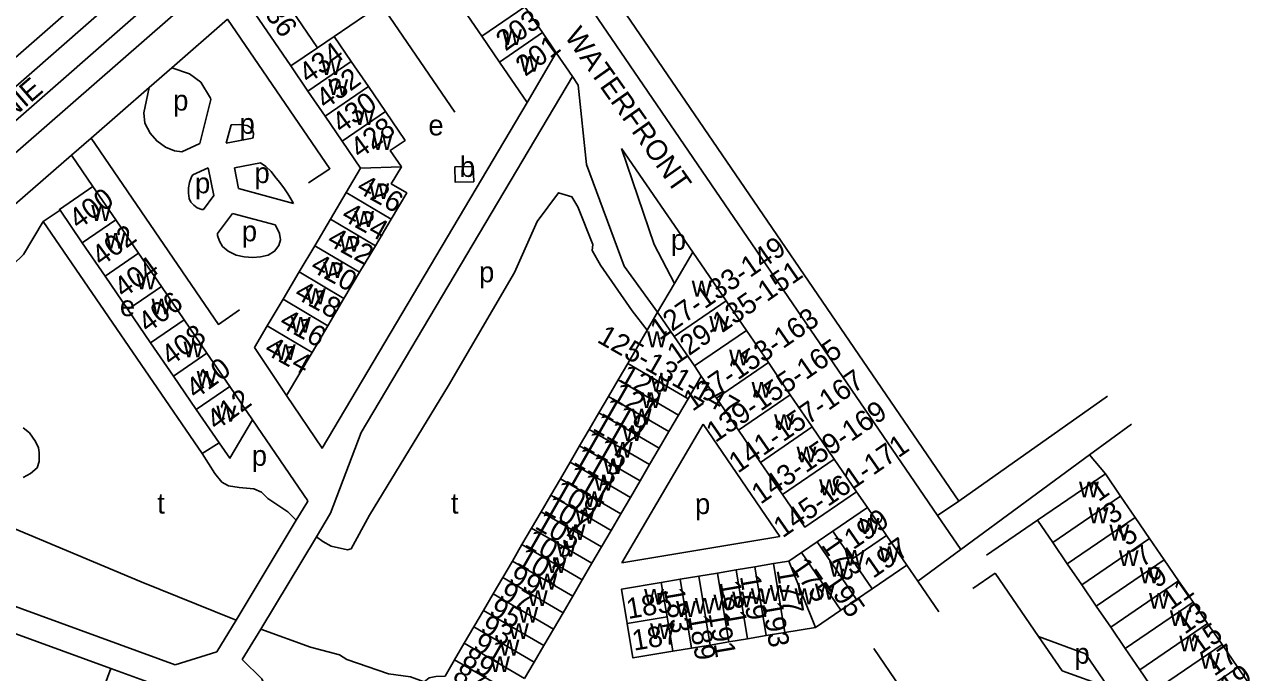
# Model space of a CAD drawing. Extents: x 154320 to 156262, y 382651 to 384180.
# Drawn here: x 156007.7 to 156246.7, y 383180.7 to 383306.8 of the extents above; entities that cross this region are included whole.
import ezdxf

# ---------------------------------------------------------------- set-up
doc = ezdxf.new("R2010")
doc.units = 0
for name, color, linetype in [('BLT_Basislijn', 7, 'Continuous'), ('BLT_Bebouwing', 7, 'Continuous'), ('BLT_Centroide', 7, 'Continuous'), ('BLT_Huisnummer', 7, 'Continuous'), ('BLT_Huisnummer_ tussenligend', 7, 'Continuous'), ('BLT_Huisnummer_reeks', 7, 'Continuous'), ('BLT_Onderverdeling_panden', 7, 'Continuous'), ('BLT_Straatnaam', 7, 'Continuous')]:
    doc.layers.add(name, color=color, linetype=linetype)

msp = doc.modelspace()

# ---------------------------------------------------------------- linework, layer by layer
at = {"layer": 'BLT_Basislijn'}
for p, q in [((156057.41, 383339.79), (155935.41, 383232.93)), ((155937.39, 383240.46), (156050.24, 383339.15)), ((156060.26, 383335.64), (155938.63, 383229.11)), ((155946.6, 383229.91), (156059.86, 383328.96)), ((156036.31, 383298.35), (156047.19, 383307.85)), ((156111.11, 383301.29), (156114.23, 383296.66)), ((156031.9, 383294.51), (156036.31, 383298.35)), ((156073.18, 383227.36), (156114.23, 383296.66)), ((156114.23, 383296.66), (156115.37, 383294.97)), ((156020.62, 383284.67), (156031.9, 383294.51)), ((156016.82, 383281.36), (156020.62, 383284.67)), ((156123.8, 383282.68), (156137.65, 383262.47)), ((155942.48, 383216.52), (156016.82, 383281.36)), ((156021, 383275.24), (156016.82, 383281.36)), ((156049.33, 383274.89), (156060.01, 383271.96)), ((156011.34, 383268.41), (156014.6, 383270.63)), ((156042.22, 383223.28), (156011.34, 383268.41)), ((156048.17, 383270.02), (156056.42, 383267.76)), ((156218.33, 383234.45), (156189.4, 383214.02)), ((156052.03, 383229.82), (156062.77, 383214.03)), ((156222.99, 383228.97), (156214.82, 383223.01)), ((156045.52, 383225.37), (156042.22, 383223.28)), ((156217.89, 383219.31), (156214.82, 383223.01)), ((156171.6, 383212.78), (156169.51, 383215.84)), ((156185.27, 383211.2), (156189.78, 383204.59)), ((156060.54, 383210.27), (156048.84, 383190.84)), ((156204.7, 383210.29), (156194.79, 383203.51)), ((156064.46, 383207.08), (156053.63, 383189.1)), ((156181.42, 383198.44), (156179.28, 383201.56)), ((156181.42, 383198.44), (156185.5, 383192.48)), ((156048.84, 383190.84), (156045.11, 383184.66)), ((156053.63, 383189.1), (156050.04, 383183.15)), ((156045.11, 383184.66), (156037.02, 383182.14)), ((156177.97, 383177.79), (156172.89, 383185.3)), ((156022.72, 383176.68), (156024.45, 383181.39)), ((156036.57, 383176.99), (156024.45, 383181.39))]:
    msp.add_line(p, q, dxfattribs=at)
for points in [[(156189.4, 383214.02), (156098.19, 383347.67)], [(156185.27, 383211.2), (156093.74, 383345.32)], [(156067.93, 383304.46), (156077.07, 383310.67), (156091.4, 383289.75)], [(156062.9, 383275.95), (156067.08, 383278.7), (156047.19, 383307.85)], [(156036.31, 383298.35), (156039.76, 383297.21), (156041.95, 383295.54), (156043.89, 383292.43), (156043.95, 383292.17)], [(156038.3, 383282.02), (156036.87, 383282.21), (156035.08, 383282.94), (156033.42, 383284.13), (156032.12, 383285.62), (156031.12, 383287.55), (156030.89, 383289.59), (156031.9, 383294.51)], [(156130.82, 383250.76), (156124.28, 383259.77), (156117, 383279.53), (156115.37, 383294.97)], [(156043.95, 383292.17), (156041.76, 383283.65), (156038.3, 383282.02)], [(156058.63, 383234.59), (156065.55, 383224.29), (156105.42, 383291.59)], [(156047.85, 383287.25), (156046.93, 383283.68)], [(156047.85, 383287.25), (156049.42, 383287.29), (156050.97, 383287.14), (156051.58, 383286.77), (156051.95, 383286.32), (156052.2, 383285.59), (156052.15, 383284.88), (156052.05, 383284.66)], [(156049.52, 383251.22), (156045.4, 383248.4), (156020.62, 383284.67)], [(156046.93, 383283.68), (156052.05, 383284.66)], [(156123.8, 383282.68), (156130.16, 383263.99), (156134.1, 383256.39)], [(156048.51, 383278.89), (156053.59, 383279.87)], [(156053.59, 383279.87), (156054.59, 383279.12), (156055.63, 383278.18), (156056.38, 383277.23), (156057.27, 383276.1), (156058.11, 383275), (156058.89, 383273.8), (156059.49, 383272.83), (156060.01, 383271.96)], [(156042.47, 383270.76), (156042.18, 383270.79), (156041.29, 383271.13), (156040.63, 383271.59), (156040.06, 383272.23), (156039.74, 383272.9), (156039.59, 383273.96), (156039.61, 383275.02), (156039.78, 383276.05), (156040.18, 383277.14), (156040.43, 383277.49)], [(156043.4, 383278.89), (156040.43, 383277.49)], [(156043.4, 383278.89), (156044.52, 383273.48), (156042.47, 383270.76)], [(156048.51, 383278.89), (156049.33, 383274.89)], [(156128.8, 383247.3), (156125.88, 383251.06), (156119.69, 383259.91), (156118.07, 383262.77), (156118.2, 383263.93), (156115.32, 383271.29), (156114.16, 383273.25), (156111.53, 383274.02), (156107.4, 383268.42), (156102.97, 383258.52), (156090.17, 383236.5), (156074.81, 383211.3), (156071.19, 383204.72), (156070.5, 383204.54), (156067.32, 383205.25), (156065.68, 383206.13), (156064.46, 383207.08)], [(156011.34, 383268.41), (156007.52, 383261.99), (155996.87, 383251.78), (155973.79, 383231.77), (155972.23, 383231.52), (155970.88, 383231.79), (155962.55, 383224.45), (155964.02, 383223.22), (155980.92, 383216.77), (155985.15, 383215.38), (155987.15, 383215.65), (156001.25, 383210.49), (156030.38, 383198.26), (156048.23, 383191.07), (156048.84, 383190.84)], [(156048.17, 383270.02), (156045.21, 383266.1)], [(156056.42, 383267.76), (156056.77, 383267.21), (156057.27, 383266.08), (156057.48, 383264.85), (156057.14, 383263.74), (156056.31, 383262.65), (156055.09, 383261.91), (156053.57, 383261.59), (156052.06, 383261.43), (156050.41, 383261.57), (156048.87, 383261.87), (156047.3, 383262.64), (156046.21, 383263.59), (156045.58, 383264.61), (156045.25, 383265.69), (156045.21, 383266.1)], [(156007.4, 383228.29), (156008.63, 383227.29), (156009.83, 383225.59), (156010.41, 383224.37), (156010.54, 383223.49), (156010.56, 383221.73), (156010.14, 383220.49), (156008.87, 383219.39), (156007.44, 383218.57)], [(156073.18, 383227.36), (156067.21, 383211.65), (156064.46, 383207.08)], [(156123.87, 383201.97), (156139.64, 383229)], [(156139.64, 383229), (156154.61, 383207.11)], [(156060.54, 383210.27), (156058.91, 383211.92), (156054.99, 383214.52), (156053.8, 383215.75), (156052.26, 383216.37), (156049.41, 383216.67), (156047.33, 383216.97), (156046.08, 383217.7), (156044.71, 383219.36), (156042.22, 383223.28)], [(156214.82, 383223.01), (156189.78, 383204.59)], [(156062.77, 383214.03), (156062.7, 383213.85), (156060.54, 383210.27)], [(156189.4, 383214.02), (156185.27, 383211.2)], [(155960.94, 383209.9), (156026.16, 383186.09), (156037.02, 383182.14)], [(156154.61, 383207.11), (156123.87, 383201.97)], [(156024.45, 383181.39), (155960.61, 383204.7), (155940.61, 383200.09)], [(156189.78, 383204.59), (156181.42, 383198.44)], [(156196.45, 383200.01), (156192.09, 383197.02)], [(156204.88, 383187.64), (156196.45, 383200.01)], [(156053.63, 383189.1), (156063.31, 383185.56), (156068.94, 383184.05), (156070.37, 383183.18), (156078.47, 383180.38), (156082.76, 383179.81), (156085.39, 383178.84), (156086.36, 383179.59), (156087.7, 383179.88), (156089.47, 383179.91)], [(156204.88, 383187.64), (156214.01, 383184.3), (156218.52, 383177.7)], [(156218.52, 383177.7), (156209.49, 383180.97), (156204.88, 383187.64)], [(156055.87, 383175.29), (156053.84, 383179.39), (156050.04, 383183.15)]]:
    msp.add_lwpolyline(points, dxfattribs=at)
at = {"layer": 'BLT_Bebouwing'}
for p, q in [((156064.64, 383302.23), (156059.65, 383309.57)), ((156093.18, 383309.52), (156096.61, 383304.5)), ((156108.44, 383305.2), (156105.01, 383310.22)), ((156067.93, 383304.46), (156064.64, 383302.23)), ((156071.24, 383299.59), (156067.93, 383304.46)), ((156096.61, 383304.5), (156100.04, 383299.47)), ((156111.11, 383301.29), (156108.44, 383305.2)), ((156074.56, 383294.71), (156071.24, 383299.59)), ((156059.47, 383298.72), (156062.8, 383293.84)), ((156077.89, 383289.82), (156074.56, 383294.71)), ((156062.8, 383293.84), (156066.14, 383288.96)), ((156066.14, 383288.96), (156069.47, 383284.07)), ((156069.47, 383284.07), (156073.06, 383278.81)), ((156073.06, 383278.81), (156070.26, 383274.07)), ((156070.26, 383274.07), (156067.19, 383268.89)), ((156014.6, 383270.63), (156018.92, 383264.3)), ((156029.87, 383262.26), (156025.44, 383268.75)), ((156067.19, 383268.89), (156064.13, 383263.73)), ((156075.92, 383263.71), (156078.99, 383268.89)), ((156018.92, 383264.3), (156023.36, 383257.81)), ((156064.13, 383263.73), (156061.09, 383258.61)), ((156072.86, 383258.55), (156075.92, 383263.71)), ((156034.3, 383255.77), (156029.87, 383262.26)), ((156061.09, 383258.61), (156057.96, 383253.32)), ((156069.82, 383253.43), (156072.86, 383258.55)), ((156023.36, 383257.81), (156027.79, 383251.32)), ((156134.1, 383256.39), (156130.82, 383250.76)), ((156038.73, 383249.29), (156034.3, 383255.77)), ((156027.79, 383251.32), (156032.22, 383244.83)), ((156057.96, 383253.32), (156054.89, 383248.14)), ((156066.68, 383248.15), (156069.82, 383253.43)), ((156043.17, 383242.8), (156038.73, 383249.29)), ((156130.82, 383250.76), (156128.8, 383247.3)), ((156063.6, 383242.96), (156066.68, 383248.15)), ((156128.8, 383247.3), (156125, 383240.79)), ((156032.22, 383244.83), (156036.65, 383238.35)), ((156047.6, 383236.31), (156043.17, 383242.8)), ((156036.65, 383238.35), (156041.08, 383231.86)), ((156207.66, 383205.95), (156204.7, 383210.29)), ((156210.48, 383201.82), (156207.66, 383205.95)), ((156213.29, 383197.7), (156210.48, 383201.82)), ((156216.11, 383193.57), (156213.29, 383197.7)), ((156218.93, 383189.44), (156216.11, 383193.57)), ((156221.76, 383185.31), (156218.93, 383189.44)), ((156224.57, 383181.19), (156221.76, 383185.31)), ((156227.39, 383177.05), (156224.57, 383181.19))]:
    msp.add_line(p, q, dxfattribs=at)
for points in [[(156059.47, 383298.72), (156050.98, 383311.16)], [(156105.42, 383291.59), (156111.11, 383301.29)], [(156100.04, 383299.47), (156105.42, 383291.59)], [(156080.98, 383279.09), (156078.81, 383282.25), (156081.7, 383284.23), (156077.89, 383289.82)], [(156078.99, 383268.89), (156082.02, 383273.99), (156079.01, 383275.78), (156080.98, 383279.09)], [(156021, 383275.24), (156014.49, 383270.79), (156014.6, 383270.63)], [(156025.44, 383268.75), (156021, 383275.24)], [(156137.65, 383262.47), (156134.1, 383256.39)], [(156144.14, 383252.97), (156137.65, 383262.47)], [(156148.07, 383247.21), (156144.14, 383252.97)], [(156054.89, 383248.14), (156052.39, 383243.93)], [(156152.35, 383240.96), (156148.07, 383247.21)], [(156052.39, 383243.93), (156058.63, 383234.59)], [(156058.63, 383234.59), (156063.6, 383242.96)], [(156125, 383240.79), (156123.13, 383237.59)], [(156156.62, 383234.71), (156152.35, 383240.96)], [(156123.13, 383237.59), (156121.26, 383234.38)], [(156136.74, 383233.94), (156139.31, 383238.34)], [(156139.31, 383238.34), (156142.24, 383234.06)], [(156052.03, 383229.82), (156047.6, 383236.31)], [(156121.26, 383234.38), (156119.39, 383231.18)], [(156160.89, 383228.45), (156156.62, 383234.71)], [(156134.87, 383230.73), (156136.74, 383233.94)], [(156142.24, 383234.06), (156146.52, 383227.8)], [(156041.08, 383231.86), (156045.52, 383225.37)], [(156045.52, 383225.37), (156047.62, 383222.34), (156052.03, 383229.82)], [(156119.39, 383231.18), (156117.52, 383227.97)], [(156133, 383227.53), (156134.87, 383230.73)], [(156117.52, 383227.97), (156115.65, 383224.77)], [(156131.13, 383224.33), (156133, 383227.53)], [(156146.52, 383227.8), (156150.79, 383221.55)], [(156165.17, 383222.2), (156160.89, 383228.45)], [(156115.65, 383224.77), (156113.78, 383221.56)], [(156129.26, 383221.12), (156131.13, 383224.33)], [(156113.78, 383221.56), (156111.91, 383218.36)], [(156127.39, 383217.92), (156129.26, 383221.12)], [(156150.79, 383221.55), (156155.07, 383215.3)], [(156169.51, 383215.84), (156165.17, 383222.2)], [(156111.91, 383218.36), (156110.04, 383215.16)], [(156125.52, 383214.71), (156127.39, 383217.92)], [(156204.7, 383210.29), (156217.89, 383219.31)], [(156217.89, 383219.31), (156220.86, 383214.97)], [(156155.07, 383215.3), (156159.41, 383208.95), (156169.51, 383215.84)], [(156110.04, 383215.16), (156108.17, 383211.95)], [(156123.65, 383211.51), (156125.52, 383214.71)], [(156220.86, 383214.97), (156223.68, 383210.84)], [(156108.17, 383211.95), (156106.3, 383208.75)], [(156121.78, 383208.31), (156123.65, 383211.51)], [(156171.6, 383212.78), (156164.87, 383208.18)], [(156175.33, 383207.34), (156171.6, 383212.78)], [(156223.68, 383210.84), (156226.5, 383206.71)], [(156106.3, 383208.75), (156104.43, 383205.54)], [(156119.91, 383205.1), (156121.78, 383208.31)], [(156164.87, 383208.18), (156161.82, 383206.1)], [(156161.82, 383206.1), (156158.78, 383204.02)], [(156179.28, 383201.56), (156175.33, 383207.34)], [(156226.5, 383206.71), (156229.32, 383202.59)], [(156104.43, 383205.54), (156102.56, 383202.34)], [(156118.04, 383201.9), (156119.91, 383205.1)], [(156158.78, 383204.02), (156156.3, 383202.32)], [(156102.56, 383202.34), (156100.69, 383199.13)], [(156116.17, 383198.69), (156118.04, 383201.9)], [(156149.71, 383201.22), (156146.07, 383200.61)], [(156153.34, 383201.83), (156149.71, 383201.22)], [(156156.3, 383202.32), (156153.34, 383201.83)], [(156172.54, 383196.96), (156179.28, 383201.56)], [(156229.32, 383202.59), (156232.14, 383198.46)], [(156100.69, 383199.13), (156098.82, 383195.93)], [(156114.3, 383195.49), (156116.17, 383198.69)], [(156135.17, 383198.79), (156131.53, 383198.18)], [(156138.8, 383199.4), (156135.17, 383198.79)], [(156142.44, 383200.01), (156138.8, 383199.4)], [(156146.07, 383200.61), (156142.44, 383200.01)], [(156131.53, 383198.18), (156123.79, 383196.89), (156124.91, 383190.19)], [(156169.49, 383194.88), (156172.54, 383196.96)], [(156232.14, 383198.46), (156234.96, 383194.33)], [(156098.82, 383195.93), (156096.95, 383192.73)], [(156112.43, 383192.28), (156114.3, 383195.49)], [(156166.44, 383192.8), (156169.49, 383194.88)], [(156234.96, 383194.33), (156237.78, 383190.21)], [(156096.95, 383192.73), (156095.08, 383189.52)], [(156110.56, 383189.08), (156112.43, 383192.28)], [(156161.49, 383189.41), (156166.44, 383192.8)], [(156095.08, 383189.52), (156093.21, 383186.32)], [(156108.69, 383185.88), (156110.56, 383189.08)], [(156124.91, 383190.19), (156126.02, 383183.48), (156133.77, 383184.78)], [(156155.58, 383188.43), (156161.49, 383189.41)], [(156237.78, 383190.21), (156240.6, 383186.08)], [(156141.04, 383185.99), (156144.68, 383186.6)], [(156144.68, 383186.6), (156148.31, 383187.21)], [(156148.31, 383187.21), (156151.95, 383187.82)], [(156151.95, 383187.82), (156155.58, 383188.43)], [(156093.21, 383186.32), (156091.34, 383183.11)], [(156106.82, 383182.67), (156108.69, 383185.88)], [(156133.77, 383184.78), (156137.41, 383185.39)], [(156137.41, 383185.39), (156141.04, 383185.99)], [(156240.6, 383186.08), (156243.64, 383181.62)], [(156091.34, 383183.11), (156089.47, 383179.91)], [(156104.95, 383179.47), (156106.82, 383182.67)], [(156243.64, 383181.62), (156246.68, 383177.17)]]:
    msp.add_lwpolyline(points, dxfattribs=at)
msp.add_lwpolyline([(156091.37, 383279.06), (156091.45, 383276.08), (156095.04, 383276.18), (156094.95, 383279.15)], close=True, dxfattribs=at)
at = {"layer": 'BLT_Onderverdeling_panden'}
for p, q in [((156096.61, 383304.5), (156105.01, 383310.22)), ((156108.44, 383305.2), (156100.04, 383299.47)), ((156059.47, 383298.72), (156064.64, 383302.23)), ((156071.24, 383299.59), (156062.8, 383293.84)), ((156066.14, 383288.96), (156074.56, 383294.71)), ((156077.89, 383289.82), (156069.47, 383284.07)), ((156073.06, 383278.81), (156080.98, 383279.09)), ((156078.99, 383268.89), (156070.26, 383274.07)), ((156018.92, 383264.3), (156025.44, 383268.75)), ((156067.19, 383268.89), (156075.92, 383263.71)), ((156072.86, 383258.55), (156064.13, 383263.73)), ((156023.36, 383257.81), (156029.87, 383262.26)), ((156061.09, 383258.61), (156069.82, 383253.43)), ((156034.3, 383255.77), (156027.79, 383251.32)), ((156066.68, 383248.15), (156057.96, 383253.32)), ((156032.22, 383244.83), (156038.73, 383249.29)), ((156054.89, 383248.14), (156063.6, 383242.96)), ((156043.17, 383242.8), (156036.65, 383238.35)), ((156041.08, 383231.86), (156047.6, 383236.31))]:
    msp.add_line(p, q, dxfattribs=at)
for points in [[(156144.14, 383252.97), (156134.03, 383246.06)], [(156130.82, 383250.76), (156134.03, 383246.06)], [(156148.07, 383247.21), (156137.97, 383240.31)], [(156134.03, 383246.06), (156137.97, 383240.31)], [(156125, 383240.79), (156136.74, 383233.94)], [(156137.97, 383240.31), (156139.31, 383238.34)], [(156152.35, 383240.96), (156142.24, 383234.06)], [(156123.13, 383237.59), (156134.87, 383230.73)], [(156121.26, 383234.38), (156133, 383227.53)], [(156156.62, 383234.71), (156146.52, 383227.8)], [(156119.39, 383231.18), (156131.13, 383224.33)], [(156117.52, 383227.97), (156129.26, 383221.12)], [(156160.89, 383228.45), (156150.79, 383221.55)], [(156115.65, 383224.77), (156127.39, 383217.92)], [(156113.78, 383221.56), (156125.52, 383214.71)], [(156165.17, 383222.2), (156155.07, 383215.3)], [(156111.91, 383218.36), (156123.65, 383211.51)], [(156110.04, 383215.16), (156121.78, 383208.31)], [(156220.86, 383214.97), (156207.66, 383205.95)], [(156108.17, 383211.95), (156119.91, 383205.1)], [(156223.68, 383210.84), (156210.48, 383201.82)], [(156106.3, 383208.75), (156118.04, 383201.9)], [(156168.59, 383202.73), (156164.87, 383208.18)], [(156169.49, 383194.88), (156161.82, 383206.1)], [(156175.33, 383207.34), (156168.59, 383202.73)], [(156226.5, 383206.71), (156213.29, 383197.7)], [(156104.43, 383205.54), (156116.17, 383198.69)], [(156166.44, 383192.8), (156158.78, 383204.02)], [(156102.56, 383202.34), (156114.3, 383195.49)], [(156151.95, 383187.82), (156149.71, 383201.22)], [(156155.58, 383188.43), (156153.34, 383201.83)], [(156156.3, 383202.32), (156161.49, 383189.41)], [(156172.54, 383196.96), (156168.59, 383202.73)], [(156229.32, 383202.59), (156216.11, 383193.57)], [(156100.69, 383199.13), (156112.43, 383192.28)], [(156137.41, 383185.39), (156135.17, 383198.79)], [(156141.04, 383185.99), (156138.8, 383199.4)], [(156144.68, 383186.6), (156142.44, 383200.01)], [(156148.31, 383187.21), (156146.07, 383200.61)], [(156132.65, 383191.48), (156131.53, 383198.18)], [(156232.14, 383198.46), (156218.93, 383189.44)], [(156098.82, 383195.93), (156110.56, 383189.08)], [(156234.96, 383194.33), (156221.76, 383185.31)], [(156096.95, 383192.73), (156108.69, 383185.88)], [(156124.91, 383190.19), (156132.65, 383191.48)], [(156133.77, 383184.78), (156132.65, 383191.48)], [(156095.08, 383189.52), (156106.82, 383182.67)], [(156237.78, 383190.21), (156224.57, 383181.19)], [(156093.21, 383186.32), (156104.95, 383179.47)], [(156240.6, 383186.08), (156227.39, 383177.05)], [(156091.34, 383183.11), (156103.08, 383176.26)], [(156243.64, 383181.62), (156232.91, 383174.29)]]:
    msp.add_lwpolyline(points, dxfattribs=at)

# ---------------------------------------------------------------- texts
at = {"layer": 'BLT_Centroide'}
for s, p in [('w', (156100.54, 383302.83)), ('w', (156065.37, 383296.96)), ('w', (156103.98, 383297.61)), ('w', (156066.74, 383293.08)), ('w', (156071.83, 383287.25)), ('w', (156075.37, 383282.36)), ('b', (156092.3, 383277.13)), ('w', (156074.71, 383272.83)), ('w', (156020.65, 383268.57)), ('w', (156071.77, 383267.42)), ('w', (156023.43, 383263.15)), ('w', (156068.96, 383262.59)), ('w', (156029.42, 383255.23)), ('w', (156065.74, 383257.48)), ('w', (156062.38, 383252.36)), ('w', (156032.37, 383250.36)), ('w', (156059.46, 383246.8)), ('w', (156038.59, 383242)), ('w', (156056.54, 383241.5)), ('w', (156041.14, 383236.28)), ('w', (156044.97, 383229.52))]:
    msp.add_text(s, height=4, rotation=359.5, dxfattribs=at).set_placement(p)
for s, p in [('p', (156036.6, 383290.03)), ('p', (156049.51, 383285.5)), ('e', (156086.23, 383285.2)), ('p', (156052.41, 383275.91)), ('p', (156040.84, 383273.93)), ('p', (156049.95, 383264.58)), ('p', (156133.39, 383262.92)), ('p', (156096.08, 383256.61)), ('w', (156137.44, 383253.82)), ('e', (156026.24, 383250.01)), ('w', (156140.85, 383247)), ('w', (156128.76, 383243.97)), ('w', (156144.71, 383240.44)), ('w', (156129.45, 383235.32)), ('w', (156149.08, 383234.13)), ('w', (156127.62, 383232.1)), ('w', (156125.78, 383228.91)), ('w', (156153.46, 383227.82)), ('w', (156123.95, 383225.69)), ('w', (156122.11, 383222.47)), ('p', (156051.88, 383220.87)), ('w', (156157.83, 383221.54)), ('w', (156120.26, 383219.26)), ('w', (156118.43, 383216.07)), ('w', (156162.23, 383215.16)), ('w', (156212.76, 383214.72)), ('t', (156033.49, 383211.57)), ('t', (156090.61, 383211.57)), ('w', (156116.59, 383212.85)), ('p', (156138.08, 383211.48)), ('w', (156114.76, 383209.63)), ('w', (156170.09, 383207.63)), ('w', (156214.62, 383209.69)), ('w', (156112.92, 383206.41)), ('w', (156218.68, 383206.32)), ('w', (156111.09, 383203.19)), ('w', (156167.19, 383201.41)), ('w', (156173.93, 383202.1)), ('w', (156220.5, 383201.38)), ('w', (156109.25, 383200.01)), ('w', (156164.15, 383199.29)), ('w', (156224.56, 383198.01)), ('w', (156107.42, 383196.79)), ('w', (156105.58, 383193.57)), ('w', (156128.18, 383193.82)), ('w', (156145.3, 383193.33)), ('w', (156148.93, 383193.96)), ('w', (156152.61, 383194.58)), ('w', (156157.44, 383193.93)), ('w', (156161.4, 383194.85)), ('w', (156226.37, 383193.07)), ('w', (156134.4, 383191.46)), ('w', (156138.04, 383192.08)), ('w', (156141.66, 383192.71)), ('w', (156103.73, 383190.35)), ('w', (156230.43, 383189.69)), ('w', (156101.9, 383187.16)), ('w', (156129.33, 383187.16)), ('w', (156100.06, 383183.94)), ('w', (156232.25, 383184.76)), ('p', (156211.87, 383182.35)), ('w', (156236.32, 383181.38)), ('w', (156098.23, 383180.72))]:
    msp.add_text(s, height=4, dxfattribs=at).set_placement(p)
at = {"layer": 'BLT_Huisnummer'}
for s, rotation, p in [('436', 306.0883, (156052.55, 383311.17)), ('201', 36.0883, (156105.06, 383296.55)), ('434', 36.0883, (156062.89, 383295.15)), ('430', 36.0883, (156069.35, 383285.44)), ('426', 331.0883, (156072.03, 383274.31)), ('400', 36.0883, (156018.18, 383266.77)), ('422', 331.0883, (156066.29, 383264.07)), ('404', 36.0883, (156026.94, 383253.42)), ('418', 331.0883, (156059.95, 383253.7)), ('408', 36.0883, (156036.12, 383240.2)), ('414', 331.0883, (156054.11, 383242.84)), ('123', 330.2347, (156123.1, 383237.42)), ('412', 36.0883, (156044.97, 383227.63)), ('117', 330.2347, (156117.97, 383227.9)), ('113', 330.2347, (156114.24, 383221.35)), ('109', 330.2347, (156110.18, 383214.84)), ('1', 35.2347, (156216.56, 383213.76)), ('105', 330.2347, (156106.74, 383208.8)), ('199', 34.7347, (156168.85, 383204.43)), ('5', 35.2347, (156222.16, 383205.08)), ('197', 34.7347, (156172.72, 383198.84)), ('101', 330.2347, (156103.23, 383201.77)), ('175', 304.7347, (156156.5, 383201.27)), ('9', 35.2347, (156227.91, 383196.93)), ('179', 279.7349, (156146.8, 383199.38)), ('97', 330.2347, (156099.75, 383195.09)), ('185', 9.7349, (156125.08, 383191.04)), ('13', 35.2347, (156233.33, 383187.96)), ('93', 330.2347, (156096.09, 383188.67)), ('189', 279.7349, (156136.75, 383191.57)), ('187', 9.7349, (156126.2, 383184.86)), ('89', 330.2347, (156092.51, 383182.42)), ('17', 35.2347, (156239.08, 383179.8))]:
    msp.add_text(s, height=4, rotation=rotation, dxfattribs=at).set_placement(p)
at = {"layer": 'BLT_Huisnummer_ tussenligend'}
for s, rotation, p in [('203', 36.0883, (156101.24, 383301.48)), ('432', 36.0883, (156066.23, 383290.17)), ('428', 36.0883, (156072.9, 383280.56)), ('424', 331.0883, (156069.09, 383268.9)), ('402', 36.0883, (156022.61, 383259.59)), ('420', 331.0883, (156063.06, 383258.96)), ('406', 36.0883, (156031.64, 383246.63)), ('416', 331.0883, (156057.03, 383248.14)), ('410', 36.0883, (156040.94, 383233.74)), ('121', 330.2347, (156121.6, 383233.89)), ('119', 330.2347, (156119.68, 383230.88)), ('115', 330.2347, (156116.04, 383224.49)), ('111', 330.2347, (156112.72, 383217.77)), ('107', 330.2347, (156108.5, 383211.92)), ('3', 35.2347, (156219.17, 383209.31)), ('103', 330.2347, (156104.74, 383205.32)), ('173', 304.7347, (156162.51, 383205.44)), ('7', 35.2347, (156225.03, 383201)), ('99', 330.2347, (156101.6, 383198.32)), ('177', 279.7349, (156153.91, 383200.61)), ('195', 304.7347, (156163.04, 383198.32)), ('11', 35.2347, (156230.58, 383192.64)), ('183', 279.7349, (156132, 383196.84)), ('181', 279.7349, (156142.86, 383198.25)), ('95', 330.2347, (156097.81, 383192.03)), ('193', 279.7349, (156151.09, 383194.09)), ('191', 279.7349, (156140.68, 383192.14)), ('15', 35.2347, (156236.18, 383183.92)), ('91', 330.2347, (156094.66, 383185.25)), ('87', 330.2347, (156090.69, 383179.25)), ('19', 35.2347, (156241.89, 383175.83))]:
    msp.add_text(s, height=4, rotation=rotation, dxfattribs=at).set_placement(p)
at = {"layer": 'BLT_Huisnummer_reeks'}
for s, rotation, p in [('127-133-149', 34.7347, (156131.17, 383245.2)), ('129-135-151', 34.7347, (156134.45, 383240.49)), ('137-153-163', 34.7347, (156137.59, 383231.36)), ('125-131-147', 330.2347, (156118.83, 383245.06)), ('139-155-165', 34.7347, (156142.04, 383225.29)), ('141-157-167', 34.7347, (156146.42, 383219.32)), ('143-159-169', 34.7347, (156150.84, 383213.27)), ('145-161-171', 34.7347, (156155.12, 383206.72))]:
    msp.add_text(s, height=4, rotation=rotation, dxfattribs=at).set_placement(p)
at = {"layer": 'BLT_Straatnaam'}
for s, rotation, p in [('WATERFRONT', 305.2347, (156112.58, 383304.49)), ('WATERLINIE', 40.9083, (155986.84, 383272.37))]:
    msp.add_text(s, height=4, rotation=rotation, dxfattribs=at).set_placement(p)

doc.saveas('drawing.dxf')
